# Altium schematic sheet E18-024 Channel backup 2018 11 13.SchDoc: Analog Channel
size A; Author: Mark Carlson; Organization: University of British Columbia; Address1: Physics & Astronomy Department; Address2: Electronics Lab - Room 254; Address3: 6224 Agricultural Road; Address4: Vancouver BC V6T 1Z1 Canada; DocumentNumber: E18-024; Revision: 1; SheetNumber: 3; SheetTotal: 3
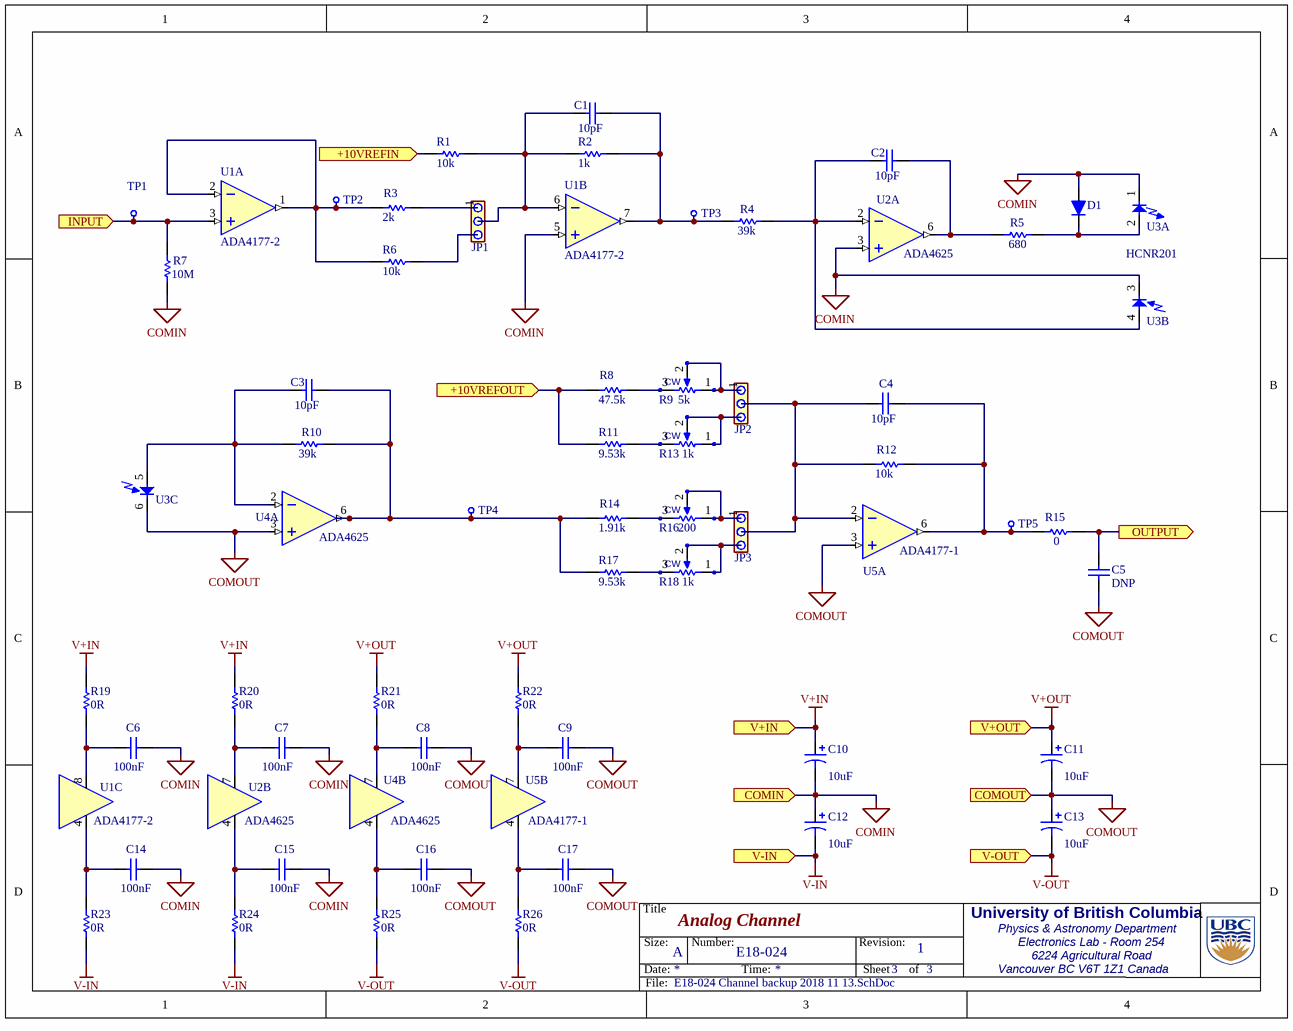
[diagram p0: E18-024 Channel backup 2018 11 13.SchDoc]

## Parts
C1  10pF  [6-0805_M]
C2  10pF  [6-0805_M]
C3  10pF  [6-0805_M]
C4  10pF  [6-0805_M]
C5  value DNP  [6-0805_M]  (hidden comment: 10pF)
C6  100nF  [6-0805_M]
C7  100nF  [6-0805_M]
C8  100nF  [6-0805_M]
C9  100nF  [6-0805_M]
C10  value 10uF  [CC3216]  (hidden comment: Tant Poly 10uF)
C11  value 10uF  [CC3216]  (hidden comment: Tant Poly 10uF)
C12  value 10uF  [CC3216]  (hidden comment: Tant Poly 10uF)
C13  value 10uF  [CC3216]  (hidden comment: Tant Poly 10uF)
C14  100nF  [6-0805_M]
C15  100nF  [6-0805_M]
C16  100nF  [6-0805_M]
C17  100nF  [6-0805_M]
D1  1N4148W  [SOD-123]  (value not drawn)
JP1  JMPR  [HDR1X3 SMD]  (value not drawn)
JP2  JMPR  [HDR1X3 SMD]  (value not drawn)
JP3  JMPR  [HDR1X3 SMD]  (value not drawn)
R1  10k  [6-0805_M]
R2  1k  [6-0805_M]
R3  2k  [6-0805_M]
R4  39k  [6-0805_M]
R5  680  [6-0805_M]
R6  10k  [6-0805_M]
R7  10M  [6-0805_M]
R8  value 47.5k  [6-0805_M]  (hidden comment: 2k)
R9  value 5k  End: CW  [POT SMD]  (hidden comment: RPot8)
R10  39k  [6-0805_M]
R11  value 9.53k  [6-0805_M]  (hidden comment: 9.09k)
R12  value 10k  [6-0805_M]  (hidden comment: 2k)
R13  value 1k  End: CW  [POT SMD]  (hidden comment: RPot8)
R14  value 1.91k  [6-0805_M]  (hidden comment: 2k)
R15  0  [6-0805_M]
R16  value 200  End: CW  [POT SMD]  (hidden comment: RPot8)
R17  value 9.53k  [6-0805_M]  (hidden comment: 9.09k)
R18  value 1k  End: CW  [POT SMD]  (hidden comment: RPot8)
R19  0R  [6-0805_M]
R20  0R  [6-0805_M]
R21  0R  [6-0805_M]
R22  0R  [6-0805_M]
R23  0R  [6-0805_M]
R24  0R  [6-0805_M]
R25  0R  [6-0805_M]
R26  0R  [6-0805_M]
TP1  Vero Eyelet Test Point  [TEST PT SMD]  (value not drawn)
TP2  Vero Eyelet Test Point  [TEST PT SMD]  (value not drawn)
TP3  Vero Eyelet Test Point  [TEST PT SMD]  (value not drawn)
TP4  Vero Eyelet Test Point  [TEST PT SMD]  (value not drawn)
TP5  Vero Eyelet Test Point  [TEST PT SMD]  (value not drawn)
U1  ADA4177-2  [SO-G8]  (parts A,B,C of 3)
U2  ADA4625  [SO-G8]  (parts A,B of 2)
U3  HCNR201  [DIP-8GW]  (parts A,B,C of 3)
U4  ADA4625  [SO-G8]  (parts A,B of 2)
U5  ADA4177-1  [SO-G8]  (parts A,B of 2)

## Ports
+10VREFIN (in), +10VREFOUT (in), COMIN (in), COMOUT (in), INPUT (in), OUTPUT (out), V+IN (in), V+OUT (in), V-IN (in), V-OUT (in)

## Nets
COMIN: C6.1 C7.1 C10.2 C12.1 C14.1 C15.1 D1.1(A) R7.1 U1.5(IN+2) U2.3(IN+) U3.1(LED_K) U3.3(PD1-K) ; port COMIN
COMOUT: C5.2 C8.1 C9.1 C11.2 C13.1 C16.1 C17.1 U3.6(PD2-K) U4.3(IN+) U5.3(IN+) ; port COMOUT
V+IN: C10.1 R19.2 R20.2 ; port V+IN
V+OUT: C11.1 R21.2 R22.2 ; port V+OUT
V-IN: C12.2 R23.1 R24.1 ; port V-IN
V-OUT: C13.2 R25.1 R26.1 ; port V-OUT
+10VREFIN: R1.2 ; port +10VREFIN
+10VREFOUT: R8.2 R11.2 ; port +10VREFOUT
INPUT: R7.2 TP1.1 U1.3(IN+1) ; port INPUT
OUTPUT: C5.1 R15.1 ; port OUTPUT
NetC1_1: C1.1 R2.1 R4.1 TP3.1 U1.7(OUT2)
NetC1_2: C1.2 JP1.2 R1.1 R2.2 U1.6(IN-2)
NetC2_1: C2.1 R5.1 U2.6(OUT)
NetC2_2: C2.2 R4.2 U2.2(IN-) U3.4(PD1-A)
NetC3_1: C3.1 R10.2 R14.2 R17.2 TP4.1 U4.6(OUT)
NetC3_2: C3.2 R10.1 U3.5(PD2-A) U4.2(IN-)
NetC4_1: C4.1 R12.1 R15.2 TP5.1 U5.6(OUT)
NetC4_2: C4.2 JP2.2 JP3.2 R12.2 U5.2(IN-)
NetC6_2: C6.2 R19.1 U1.8(V+)
NetC7_2: C7.2 R20.1 U2.7(+Vs)
NetC8_2: C8.2 R21.1 U4.7(+Vs)
NetC9_2: C9.2 R22.1 U5.7(+Vs)
NetC14_2: C14.2 R23.2 U1.4(V-)
NetC15_2: C15.2 R24.2 U2.4(-Vs)
NetC16_2: C16.2 R25.2 U4.4(-Vs)
NetC17_2: C17.2 R26.2 U5.4(-Vs)
NetD1_2: D1.2(K) R5.2 U3.2(LED_A)
NetJP1_1: JP1.1 R3.1
NetJP1_3: JP1.3 R6.1
NetJP2_1: JP2.1 R9.1 R9.2
NetJP2_3: JP2.3 R13.1 R13.2
NetJP3_1: JP3.1 R16.1 R16.2
NetJP3_3: JP3.3 R18.1 R18.2
NetR3_2: R3.2 R6.2 TP2.1 U1.1(OUT1) U1.2(IN-1)
NetR8_1: R8.1 R9.3
NetR11_1: R11.1 R13.3
NetR14_1: R14.1 R16.3
NetR17_1: R17.1 R18.3

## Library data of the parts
C1-C9 C14-C17 = Cap: Capacitor
C10-C13 = Cap Pol3: CAP TANT POLY 10UF 25V 1206
D1 = 1N4148W: High Conductance Fast Diode; Manufacturer: Fairchild Semiconductor; Revised: 11-July-2000: SIM Model Added.; Class: Discrete; SubClass: Diode - Switching; Type: SMD
JP1-JP3 = Jumper3p: 3 Pin Jumper Header; Manufacturer: Generic Components; Class: Passive
R1-R8 R10-R12 R14 R15 R17 R19-R26 = Res1: Resistor
R9 R13 R16 R18 = RPot8: SMD POT; Manufacturer: Vishay; Part Number: TS63Y; Class: Passive; SubClass: Potentiometer
TP1-TP5 = TP- Eyelet Terminal: Eyelet Test Point (white); Part Number: 20-313143A; Class: Passive
U1 = ADA4177-2: OVP and EMI Protected, Precision, / Low Noise and Bias Current Dual Op Amp; Manufacturer: Analog Devices; Class: Analog; SubClass: Operational Amp
U2 = ADA4625: 36V, 18MHz, Low Noise, JFET Op Amp; Manufacturer: Analog Devices; Class: Amplifier; SubClass: Operational Amplifier
U3 = HCNR201: Analog Optocoupler; Manufacturer: Agilent; Class: Electrical Isolation; SubClass: Opto-coupler
U4 = ADA4625: 36V, 18MHz, Low Noise, JFET Op Amp; Manufacturer: Analog Devices; Part Number: AD548KR; Class: Amplifier; SubClass: Operational Amplifier
U5 = ADA4177-1: OVP and EMI Protected, Precision, / Low Noise and Bias Current Dual Op Amp; Manufacturer: Analog Devices; Class: Amplifier; SubClass: Operational Amplifier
